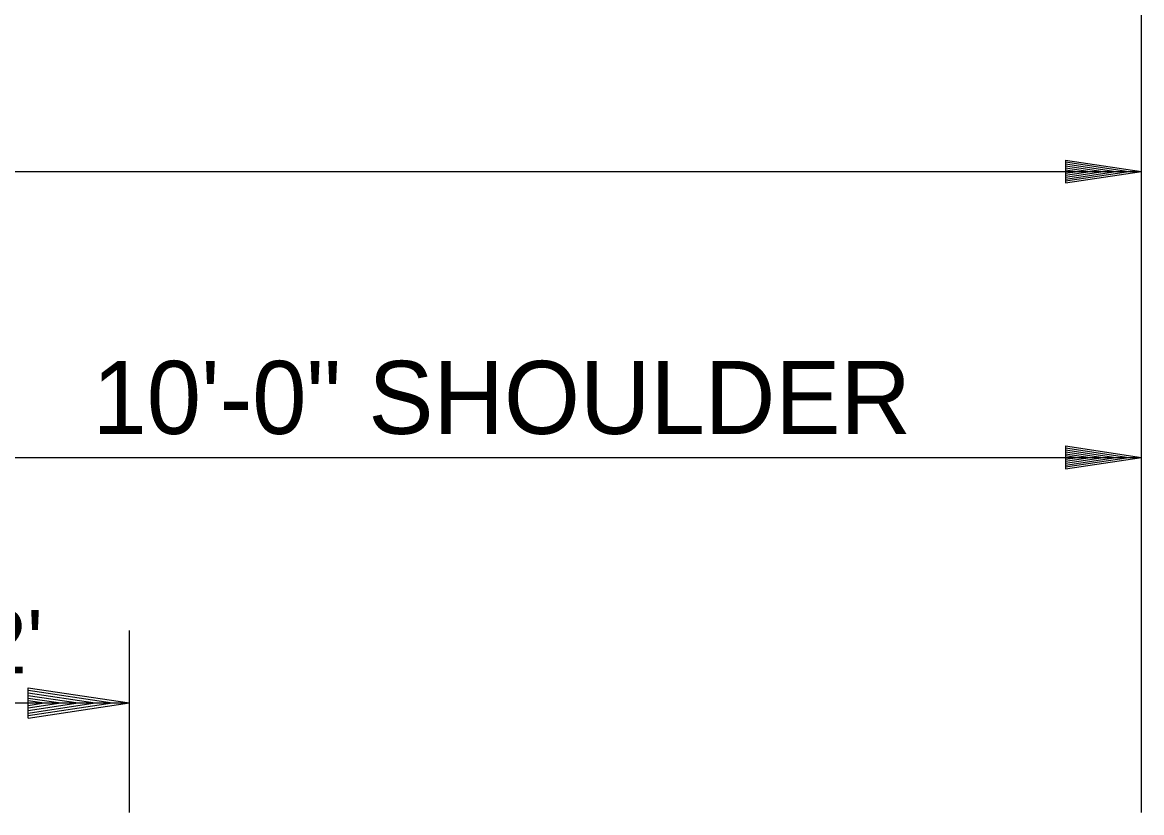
# Model space of a CAD drawing. Extents: x 1364961 to 1365294, y 367927 to 368034.
# Drawn here: x 1365056.37 to 1365065.2, y 367954.36 to 367960.59 of the extents above; entities that cross this region are included whole.
import ezdxf

# ---------------------------------------------------------------- set-up
doc = ezdxf.new("R2010")
doc.units = 0
doc.layers.add('Default', color=7, linetype='Continuous')

msp = doc.modelspace()

# ---------------------------------------------------------------- linework, layer by layer
at = {"layer": 'Default'}
for p, q in [((1365065.1971, 367954.3609), (1365065.1971, 367968.9948)), ((1365064.5971, 367959.5056), (1365065.1971, 367959.4156)), ((1365064.5971, 367959.5056), (1365064.5971, 367959.3256)), ((1365064.5971, 367959.4906), (1365065.0971, 367959.4156)), ((1365064.5971, 367959.4756), (1365064.9941, 367959.4156)), ((1365064.5971, 367959.4606), (1365064.8941, 367959.4156)), ((1365064.5971, 367959.4446), (1365064.7921, 367959.4156)), ((1365055.7923, 367959.4156), (1365065.1971, 367959.4156)), ((1365064.5971, 367959.4296), (1365064.6921, 367959.4156)), ((1365064.5971, 367959.3256), (1365065.1971, 367959.4156)), ((1365064.5971, 367959.3866), (1365064.7921, 367959.4156)), ((1365064.5971, 367959.3556), (1365064.9941, 367959.4156)), ((1365064.5971, 367959.3406), (1365065.0971, 367959.4156)), ((1365064.5971, 367959.3706), (1365064.8941, 367959.4156)), ((1365064.5971, 367959.4016), (1365064.6921, 367959.4156)), ((1365064.5971, 367957.2513), (1365065.1971, 367957.1613)), ((1365064.5971, 367957.2513), (1365064.5971, 367957.0713)), ((1365055.2141, 367957.1613), (1365065.1971, 367957.1613)), ((1365064.5971, 367957.2363), (1365065.0971, 367957.1613)), ((1365064.5971, 367957.2213), (1365064.9941, 367957.1613)), ((1365064.5971, 367957.2063), (1365064.8941, 367957.1613)), ((1365064.5971, 367957.1903), (1365064.7921, 367957.1613)), ((1365064.5971, 367957.1753), (1365064.6921, 367957.1613)), ((1365064.5971, 367957.0713), (1365065.1971, 367957.1613)), ((1365064.5971, 367957.1323), (1365064.7921, 367957.1613)), ((1365064.5971, 367957.1013), (1365064.9941, 367957.1613)), ((1365064.5971, 367957.0863), (1365065.0971, 367957.1613)), ((1365064.5971, 367957.1163), (1365064.8941, 367957.1613)), ((1365064.5971, 367957.1473), (1365064.6921, 367957.1613)), ((1365057.2141, 367954.3609), (1365057.2141, 367955.7969)), ((1365056.4141, 367955.3452), (1365057.2141, 367955.2252)), ((1365056.4141, 367955.1052), (1365056.4141, 367955.3452)), ((1365056.4141, 367955.3252), (1365057.0805, 367955.2252)), ((1365056.4141, 367955.3048), (1365056.9429, 367955.2252)), ((1365055.2141, 367955.2252), (1365057.2141, 367955.2252)), ((1365056.4141, 367955.2848), (1365056.8097, 367955.2252)), ((1365056.4141, 367955.2644), (1365056.6741, 367955.2252)), ((1365056.4141, 367955.244), (1365056.5405, 367955.2252)), ((1365056.4141, 367955.1052), (1365057.2141, 367955.2252)), ((1365056.4141, 367955.1864), (1365056.6741, 367955.2252)), ((1365056.4141, 367955.1456), (1365056.9429, 367955.2252)), ((1365056.4141, 367955.1252), (1365057.0805, 367955.2252)), ((1365056.4141, 367955.1656), (1365056.8097, 367955.2252)), ((1365056.4141, 367955.2064), (1365056.5405, 367955.2252))]:
    msp.add_line(p, q, dxfattribs=at)

# ---------------------------------------------------------------- texts
for s, height, p in [('10\'-0" SHOULDER', 0.576, (1365056.922, 367957.3463)), ("2'", 0.5, (1365056.0333, 367955.4583))]:
    msp.add_text(s, height=height, dxfattribs=at).set_placement(p)

doc.saveas('drawing.dxf')
